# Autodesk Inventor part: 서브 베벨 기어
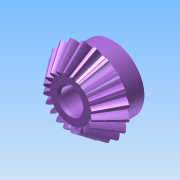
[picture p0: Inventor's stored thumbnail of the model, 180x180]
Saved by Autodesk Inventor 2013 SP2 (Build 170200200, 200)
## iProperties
Created: 2026-07
Part Number: 서브 베벨 기어
Material: Generic
Document SubType Name: Modeling
Designer: aa
Density: 1 g/cm^3
Author: aa
변환 표준: STEP AP214IS
전처리기: Build: 200, Release: 2013 SP2 Update 6 - Date: Thu 07/17/2014
전송 단위: 밀리미터
불확실성: 0.01
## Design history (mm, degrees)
node "서브 베벨기어1"
node "3D 스케치1"
body "Solid1"
node "기준1"
